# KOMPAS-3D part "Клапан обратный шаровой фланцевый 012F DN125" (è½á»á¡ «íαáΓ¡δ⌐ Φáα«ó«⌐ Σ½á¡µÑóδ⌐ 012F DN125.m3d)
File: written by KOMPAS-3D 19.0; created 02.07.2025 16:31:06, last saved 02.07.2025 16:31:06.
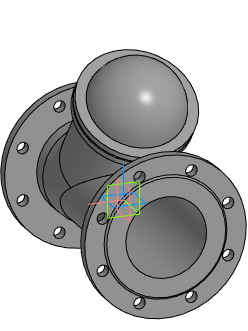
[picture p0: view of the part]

Document properties: Полное имя файла: E:\Dendor Работа Сачек\3D для проектировщиков\5.3 Тип 012F, 012F.Z Клапан обратный шаровой фланцевый\stp_Клапан обратный шаровой фланцевый 012F\Клапан обратный шаровой фланцевый 012F DN125.m3d

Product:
- Part/product: Клапан обратный шаровой фланцевый 012F DN125

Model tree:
1. Операция без истории:1  (labels: Клапан обратный шаровой фланцевый 012F DN125)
